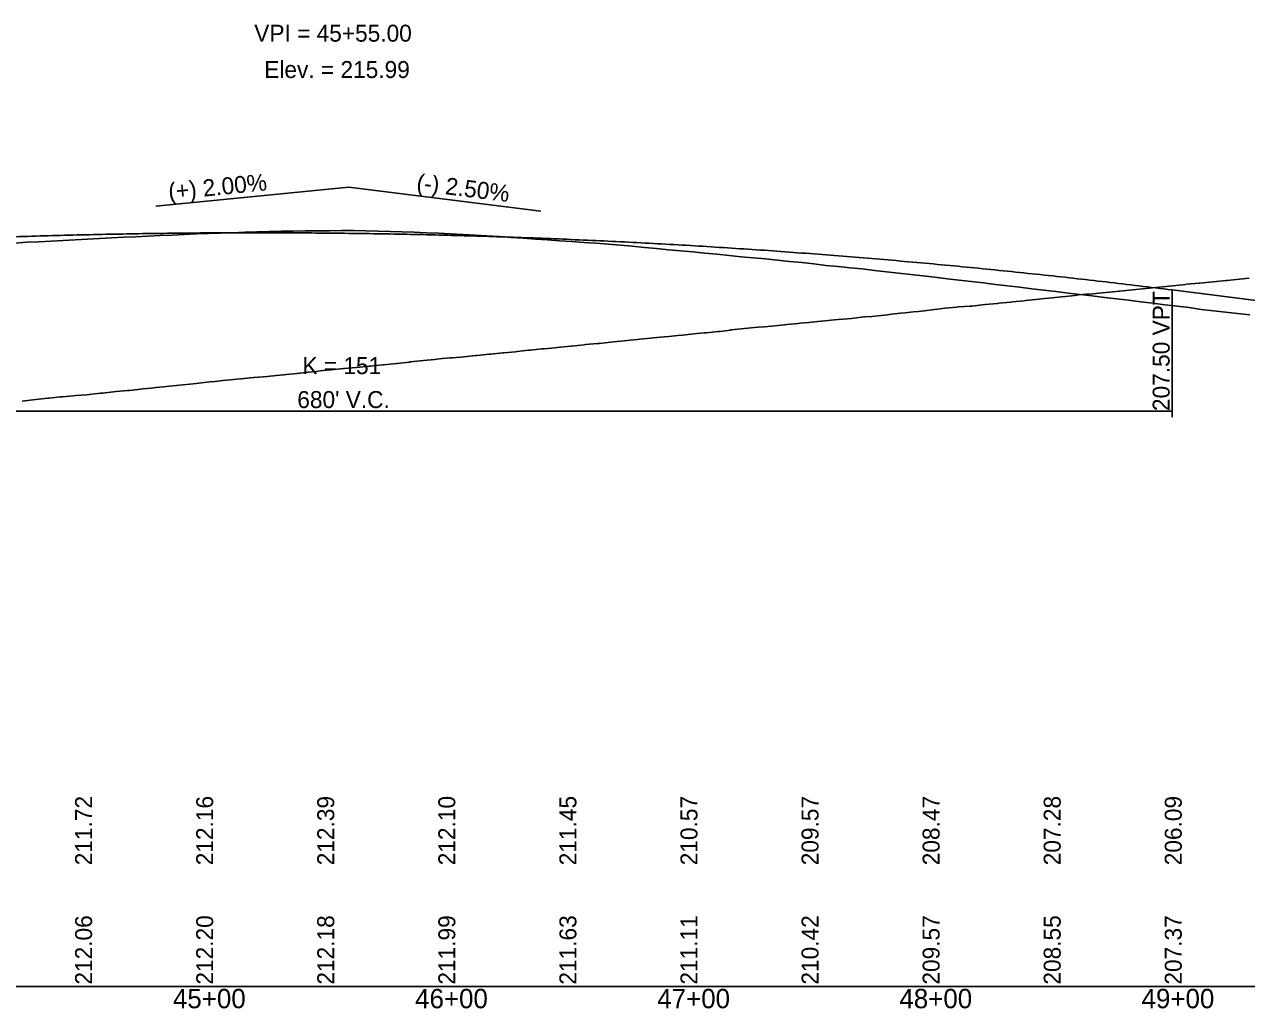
# Model space of a CAD drawing. Extents: x 1876258 to 1932803, y 754739 to 837911.
# Drawn here: x 1881084 to 1881589, y 820541 to 820947 of the extents above; entities that cross this region are included whole.
import ezdxf

# ---------------------------------------------------------------- set-up
doc = ezdxf.new("R2010")
doc.units = 0
for name, color, linetype in [('RD_DDB_GradeTX', 7, 'Continuous'), ('RD_DDB_Profile_EX', 7, 'Continuous'), ('RD_DDB_Profile_Lbl', 7, 'Continuous'), ('RD_DDB_Profile_PR', 7, 'Continuous'), ('RD_DDB_StaTX', 7, 'Continuous'), ('RD_DDB_StripGrade', 7, 'Continuous'), ('RD_DDB_VCLbl', 7, 'Continuous'), ('RD_GPK_Profile_Cell', 7, 'Continuous'), ('RD_Sketch1', 7, 'Continuous')]:
    doc.layers.add(name, color=color, linetype=linetype)

msp = doc.modelspace()

# ---------------------------------------------------------------- linework, layer by layer
at = {"layer": 'RD_DDB_GradeTX'}
for p in [(1881138.48, 820872.1), (1881297.46, 820870.14)]:
    msp.add_line(p, (1881218.08, 820880.06), dxfattribs=at)
at = {"layer": 'RD_DDB_Profile_EX'}
for points in [[(1881080.15, 820856.96), (1881085.15, 820857.27), (1881090.15, 820857.49), (1881095.15, 820857.72), (1881100.15, 820858), (1881105.15, 820858.27), (1881110.15, 820858.55), (1881115.15, 820858.83), (1881120.15, 820859.08), (1881125.15, 820859.32), (1881130.15, 820859.57), (1881135.15, 820859.85), (1881140.15, 820860.05), (1881145.15, 820860.26), (1881150.15, 820860.48), (1881155.15, 820860.71), (1881160.15, 820860.84), (1881165.15, 820860.96), (1881170.15, 820861.17), (1881175.15, 820861.41), (1881180.15, 820861.58), (1881185.15, 820861.68), (1881190.15, 820861.79), (1881195.15, 820861.89), (1881200.15, 820861.95), (1881205.15, 820862.01), (1881210.15, 820862.05), (1881215.15, 820862.06), (1881220.15, 820862.06), (1881225.15, 820862.01), (1881230.15, 820861.87), (1881235.15, 820861.72), (1881240.15, 820861.55), (1881245.15, 820861.37), (1881250.15, 820861.17), (1881255.15, 820860.97), (1881260.15, 820860.78), (1881265.15, 820860.53), (1881270.15, 820860.24), (1881275.15, 820859.95), (1881280.15, 820859.62), (1881285.15, 820859.28), (1881290.15, 820858.93), (1881295.15, 820858.58), (1881300.15, 820858.24), (1881305.15, 820857.9), (1881310.15, 820857.55), (1881315.15, 820857.21), (1881320.15, 820856.84), (1881325.15, 820856.44), (1881330.15, 820856.05), (1881335.15, 820855.61), (1881340.15, 820855.15), (1881345.15, 820854.67), (1881350.15, 820854.15), (1881355.15, 820853.68), (1881360.15, 820853.26), (1881365.15, 820852.81), (1881370.15, 820852.29), (1881375.15, 820851.78), (1881380.15, 820851.32), (1881385.15, 820850.86), (1881390.15, 820850.37)], [(1881390.15, 820850.37), (1881395.15, 820849.87), (1881400.15, 820849.38), (1881405.15, 820848.89), (1881410.15, 820848.33), (1881415.15, 820847.74), (1881420.15, 820847.24), (1881425.15, 820846.78), (1881430.15, 820846.25), (1881435.15, 820845.65), (1881440.15, 820845.08), (1881445.15, 820844.54), (1881450.15, 820843.98), (1881455.15, 820843.39), (1881460.15, 820842.8), (1881465.15, 820842.21), (1881470.15, 820841.63), (1881475.15, 820841.05), (1881480.15, 820840.47), (1881485.15, 820839.85), (1881490.15, 820839.24), (1881495.15, 820838.68), (1881500.15, 820838.11), (1881505.15, 820837.49), (1881510.15, 820836.88), (1881515.15, 820836.29), (1881520.15, 820835.69), (1881525.15, 820835.11), (1881530.15, 820834.52), (1881535.15, 820833.93), (1881540.15, 820833.33), (1881545.15, 820832.72), (1881550.15, 820832.1), (1881555.15, 820831.51), (1881560.15, 820830.94), (1881565.15, 820830.29), (1881570.15, 820829.56), (1881575.15, 820828.9), (1881580.15, 820828.36), (1881585.15, 820827.81), (1881590.15, 820827.26)]]:
    msp.add_lwpolyline(points, dxfattribs=at)
at = {"layer": 'RD_DDB_Profile_PR'}
msp.add_line((1881558.08, 820837.6), (1882275.08, 820748.07), dxfattribs=at)
msp.add_spline([(1880878.08, 820846.1), (1880891.68, 820847.42), (1880905.28, 820848.69), (1880918.88, 820849.9), (1880932.48, 820851.04), (1880946.08, 820852.12), (1880959.68, 820853.15), (1880973.28, 820854.11), (1880986.88, 820855.01), (1881000.48, 820855.85), (1881014.08, 820856.62), (1881027.68, 820857.34), (1881041.28, 820858), (1881054.88, 820858.59), (1881068.48, 820859.12), (1881082.08, 820859.59), (1881095.68, 820860.01), (1881109.28, 820860.36), (1881122.88, 820860.64), (1881136.48, 820860.87), (1881150.08, 820861.04), (1881163.68, 820861.14), (1881177.28, 820861.19), (1881190.88, 820861.17), (1881204.48, 820861.09), (1881218.08, 820860.95), (1881231.68, 820860.75), (1881245.28, 820860.49), (1881258.88, 820860.17), (1881272.48, 820859.78), (1881286.08, 820859.34), (1881299.68, 820858.83), (1881313.28, 820858.26), (1881326.88, 820857.64), (1881340.48, 820856.95), (1881354.08, 820856.2), (1881367.68, 820855.38), (1881381.28, 820854.51), (1881394.88, 820853.58), (1881408.48, 820852.58), (1881422.08, 820851.53), (1881435.68, 820850.41), (1881449.28, 820849.23), (1881462.88, 820847.99), (1881476.48, 820846.69), (1881490.08, 820845.33), (1881503.68, 820843.9), (1881517.28, 820842.42), (1881530.88, 820840.88), (1881544.48, 820839.27), (1881558.08, 820837.6)], degree=3, dxfattribs=at)
at = {"layer": 'RD_DDB_VCLbl'}
for p, q in [((1881558.08, 820785.1), (1881558.08, 820837.6)), ((1880878.08, 820787.6), (1881558.08, 820787.6))]:
    msp.add_line(p, q, dxfattribs=at)
at = {"layer": 'RD_GPK_Profile_Cell'}
msp.add_line((1878363.08, 820550.13), (1884763.08, 820550.13), dxfattribs=at)
at = {"layer": 'RD_Sketch1'}
msp.add_lwpolyline([(1881083.28, 820791.71), (1881087.58, 820792.2), (1881088.79, 820792.34), (1881093.78, 820792.93), (1881094.34, 820792.98), (1881099.06, 820793.45), (1881099.89, 820793.52), (1881104.3, 820793.87), (1881105.4, 820793.96), (1881109.86, 820794.36), (1881110.9, 820794.47), (1881115.57, 820794.95), (1881116.42, 820795.04), (1881120.99, 820795.53), (1881121.97, 820795.61), (1881126.75, 820796.03), (1881127.47, 820796.11), (1881131.14, 820796.51), (1881132.99, 820796.71), (1881136.28, 820797.07), (1881138.53, 820797.28), (1881141.55, 820797.56), (1881144.05, 820797.81), (1881146.93, 820798.1), (1881149.56, 820798.39), (1881152.39, 820798.7), (1881155.08, 820799), (1881157.27, 820799.25), (1881160.61, 820799.6), (1881162.88, 820799.83), (1881166.13, 820800.19), (1881169.2, 820800.53), (1881171.67, 820800.76), (1881173.76, 820800.96), (1881177.21, 820801.25), (1881178.92, 820801.39), (1881182.73, 820801.72), (1881184.44, 820801.86), (1881188.24, 820802.23), (1881189.75, 820802.37), (1881193.76, 820802.77), (1881195.31, 820802.92), (1881199.27, 820803.36), (1881201.36, 820803.6), (1881204.79, 820803.98), (1881206.34, 820804.15), (1881210.32, 820804.56), (1881210.88, 820804.62), (1881215.85, 820805.11), (1881216.15, 820805.14), (1881221.21, 820805.6), (1881221.37, 820805.62), (1881226.45, 820806.12), (1881226.9, 820806.16), (1881232.11, 820806.66), (1881232.42, 820806.7), (1881237.94, 820807.24), (1881238.06, 820807.25), (1881243.2, 820807.85), (1881243.45, 820807.88), (1881248.92, 820808.49), (1881248.99, 820808.5), (1881253.59, 820808.94), (1881254.51, 820809.03), (1881256.75, 820809.27), (1881260.05, 820809.54), (1881260.79, 820809.6), (1881264.33, 820809.91), (1881265.56, 820810.03), (1881270.38, 820810.5), (1881271.09, 820810.57), (1881276.07, 820811.05), (1881276.61, 820811.1), (1881281.65, 820811.59), (1881282.13, 820811.64), (1881287.01, 820812.1), (1881287.64, 820812.17), (1881292.38, 820812.68), (1881293.17, 820812.77), (1881297.8, 820813.25), (1881298.72, 820813.32), (1881303.32, 820813.68), (1881304.21, 820813.78), (1881309.73, 820814.4), (1881310.09, 820814.44), (1881315.26, 820814.98), (1881315.92, 820815.05), (1881320.81, 820815.47), (1881321.68, 820815.55), (1881326.31, 820816.02), (1881327.62, 820816.15), (1881331.83, 820816.6), (1881334.35, 820816.86), (1881337.35, 820817.18), (1881338.12, 820817.26), (1881342.89, 820817.72), (1881343.67, 820817.79), (1881348.41, 820818.25), (1881350.29, 820818.43), (1881353.94, 820818.77), (1881355.9, 820818.95), (1881359.45, 820819.31), (1881361.85, 820819.55), (1881364.99, 820819.83), (1881365.85, 820819.91), (1881370.5, 820820.39), (1881371.42, 820820.48), (1881375.59, 820821.02), (1881376, 820821.07), (1881380.11, 820821.54), (1881381.54, 820821.69), (1881385.64, 820822.13), (1881387.11, 820822.23), (1881389.77, 820822.41), (1881392.62, 820822.64), (1881395.32, 820822.86), (1881398.09, 820823.19), (1881398.94, 820823.29), (1881403.65, 820823.74), (1881404.41, 820823.81), (1881408.1, 820824.2), (1881409.18, 820824.3), (1881413.21, 820824.65), (1881414.69, 820824.79), (1881418.71, 820825.19), (1881420.22, 820825.33), (1881424.08, 820825.68), (1881425.72, 820825.86), (1881429.79, 820826.3), (1881431.27, 820826.43), (1881434.12, 820826.68), (1881436.78, 820826.95), (1881440.56, 820827.34), (1881442.28, 820827.54), (1881445.87, 820827.96), (1881447.82, 820828.16), (1881451.1, 820828.49), (1881453.35, 820828.72), (1881456.85, 820829.08), (1881458.83, 820829.34), (1881462.28, 820829.81), (1881464.39, 820830.02), (1881469.06, 820830.5), (1881469.96, 820830.56), (1881474.65, 820830.86), (1881475.43, 820830.94), (1881480.76, 820831.53), (1881480.97, 820831.55), (1881485.99, 820832.05), (1881486.49, 820832.1), (1881491.56, 820832.61), (1881492.01, 820832.65), (1881497.07, 820833.15), (1881497.53, 820833.2), (1881503.06, 820833.76), (1881504.09, 820833.86), (1881508.58, 820834.3), (1881512.49, 820834.68), (1881514.08, 820834.87), (1881517.91, 820835.33), (1881519.62, 820835.52), (1881522.43, 820835.82), (1881525.17, 820836.05), (1881526.54, 820836.16), (1881530.68, 820836.55), (1881532.41, 820836.71), (1881536.19, 820837.11), (1881536.54, 820837.15), (1881540.47, 820837.53), (1881541.72, 820837.66), (1881547.25, 820838.2), (1881547.35, 820838.21), (1881552.76, 820838.77), (1881552.83, 820838.78), (1881558.29, 820839.33), (1881558.33, 820839.33), (1881563.81, 820839.9), (1881563.88, 820839.91), (1881569.34, 820840.43), (1881569.56, 820840.45), (1881574.87, 820840.95), (1881575.1, 820840.97), (1881580.38, 820841.5), (1881580.82, 820841.55), (1881584.57, 820841.94), (1881585.92, 820842.05), (1881589.88, 820842.39)], dxfattribs=at)
msp.add_lwpolyline([(1881083.28, 820791.71), (1881087.58, 820792.2), (1881088.79, 820792.34), (1881093.78, 820792.93), (1881094.34, 820792.98), (1881099.06, 820793.45), (1881099.89, 820793.52), (1881104.3, 820793.87), (1881105.4, 820793.96), (1881109.86, 820794.36), (1881110.9, 820794.47), (1881115.57, 820794.95), (1881116.42, 820795.04), (1881120.99, 820795.53), (1881121.97, 820795.61), (1881126.75, 820796.03), (1881127.47, 820796.11), (1881131.14, 820796.51), (1881132.99, 820796.71), (1881136.28, 820797.07), (1881138.53, 820797.28), (1881141.55, 820797.56), (1881144.05, 820797.81), (1881146.93, 820798.1), (1881149.56, 820798.39), (1881152.39, 820798.7), (1881155.08, 820799), (1881157.27, 820799.25), (1881160.61, 820799.6), (1881162.88, 820799.83), (1881166.13, 820800.19), (1881169.2, 820800.53), (1881171.67, 820800.76), (1881173.76, 820800.96), (1881177.21, 820801.25), (1881178.92, 820801.39), (1881182.73, 820801.72), (1881184.44, 820801.86), (1881188.24, 820802.23), (1881189.75, 820802.37), (1881193.76, 820802.77), (1881195.31, 820802.92), (1881199.27, 820803.36), (1881201.36, 820803.6), (1881204.79, 820803.98), (1881206.34, 820804.15), (1881210.32, 820804.56), (1881210.88, 820804.62), (1881215.85, 820805.11), (1881216.15, 820805.14), (1881221.21, 820805.6), (1881221.37, 820805.62), (1881226.45, 820806.12), (1881226.9, 820806.16), (1881232.11, 820806.66), (1881232.42, 820806.7), (1881237.94, 820807.24), (1881238.06, 820807.25), (1881243.2, 820807.85), (1881243.45, 820807.88), (1881248.92, 820808.49), (1881248.99, 820808.5), (1881253.59, 820808.94), (1881254.51, 820809.03), (1881256.75, 820809.27), (1881260.05, 820809.54), (1881260.79, 820809.6), (1881264.33, 820809.91), (1881265.56, 820810.03), (1881270.38, 820810.5), (1881271.09, 820810.57), (1881276.07, 820811.05), (1881276.61, 820811.1), (1881281.65, 820811.59), (1881282.13, 820811.64), (1881287.01, 820812.1), (1881287.64, 820812.17), (1881292.38, 820812.68), (1881293.17, 820812.77), (1881297.8, 820813.25), (1881298.72, 820813.32), (1881303.32, 820813.68), (1881304.21, 820813.78), (1881309.73, 820814.4), (1881310.09, 820814.44), (1881315.26, 820814.98), (1881315.92, 820815.05), (1881320.81, 820815.47), (1881321.68, 820815.55), (1881326.31, 820816.02), (1881327.62, 820816.15), (1881331.83, 820816.6), (1881334.35, 820816.86), (1881337.35, 820817.18), (1881338.12, 820817.26), (1881342.89, 820817.72), (1881343.67, 820817.79), (1881348.41, 820818.25), (1881350.29, 820818.43), (1881353.94, 820818.77), (1881355.9, 820818.95), (1881359.45, 820819.31), (1881361.85, 820819.55), (1881364.99, 820819.83), (1881365.85, 820819.91), (1881370.5, 820820.39), (1881371.42, 820820.48), (1881375.59, 820821.02), (1881376, 820821.07), (1881380.11, 820821.54), (1881381.54, 820821.69), (1881385.64, 820822.13), (1881387.11, 820822.23), (1881389.77, 820822.41), (1881392.62, 820822.64), (1881395.32, 820822.86), (1881398.09, 820823.19), (1881398.94, 820823.29), (1881403.65, 820823.74), (1881404.41, 820823.81), (1881408.1, 820824.2), (1881409.18, 820824.3), (1881413.21, 820824.65), (1881414.69, 820824.79), (1881418.71, 820825.19), (1881420.22, 820825.33), (1881424.08, 820825.68), (1881425.72, 820825.86), (1881429.79, 820826.3), (1881431.27, 820826.43), (1881434.12, 820826.68), (1881436.78, 820826.95), (1881440.56, 820827.34), (1881442.28, 820827.54), (1881445.87, 820827.96), (1881447.82, 820828.16), (1881451.1, 820828.49), (1881453.35, 820828.72), (1881456.85, 820829.08), (1881458.83, 820829.34), (1881462.28, 820829.81), (1881464.39, 820830.02), (1881469.06, 820830.5), (1881469.96, 820830.56), (1881474.65, 820830.86), (1881475.43, 820830.94), (1881480.76, 820831.53), (1881480.97, 820831.55), (1881485.99, 820832.05), (1881486.49, 820832.1), (1881491.56, 820832.61), (1881492.01, 820832.65), (1881497.07, 820833.15), (1881497.53, 820833.2), (1881503.06, 820833.76), (1881504.09, 820833.86), (1881508.58, 820834.3), (1881512.49, 820834.68), (1881514.08, 820834.87), (1881517.91, 820835.33), (1881519.62, 820835.52), (1881522.43, 820835.82), (1881525.17, 820836.05), (1881526.54, 820836.16), (1881530.68, 820836.55), (1881532.41, 820836.71), (1881536.19, 820837.11), (1881536.54, 820837.15), (1881540.47, 820837.53), (1881541.72, 820837.66), (1881547.25, 820838.2), (1881547.35, 820838.21), (1881552.76, 820838.77), (1881552.83, 820838.78), (1881558.29, 820839.33), (1881558.33, 820839.33), (1881563.81, 820839.9), (1881563.88, 820839.91), (1881569.34, 820840.43), (1881569.56, 820840.45), (1881574.87, 820840.95), (1881575.1, 820840.97), (1881580.38, 820841.5), (1881580.82, 820841.55), (1881584.57, 820841.94), (1881585.92, 820842.05), (1881589.88, 820842.39)], dxfattribs=at)
msp.add_lwpolyline([(1881083.28, 820791.71), (1881087.58, 820792.2), (1881088.79, 820792.34), (1881093.78, 820792.93), (1881094.34, 820792.98), (1881099.06, 820793.45), (1881099.89, 820793.52), (1881104.3, 820793.87), (1881105.4, 820793.96), (1881109.86, 820794.36), (1881110.9, 820794.47), (1881115.57, 820794.95), (1881116.42, 820795.04), (1881120.99, 820795.53), (1881121.97, 820795.61), (1881126.75, 820796.03), (1881127.47, 820796.11), (1881131.14, 820796.51), (1881132.99, 820796.71), (1881136.28, 820797.07), (1881138.53, 820797.28), (1881141.55, 820797.56), (1881144.05, 820797.81), (1881146.93, 820798.1), (1881149.56, 820798.39), (1881152.39, 820798.7), (1881155.08, 820799), (1881157.27, 820799.25), (1881160.61, 820799.6), (1881162.88, 820799.83), (1881166.13, 820800.19), (1881169.2, 820800.53), (1881171.67, 820800.76), (1881173.76, 820800.96), (1881177.21, 820801.25), (1881178.92, 820801.39), (1881182.73, 820801.72), (1881184.44, 820801.86), (1881188.24, 820802.23), (1881189.75, 820802.37), (1881193.76, 820802.77), (1881195.31, 820802.92), (1881199.27, 820803.36), (1881201.36, 820803.6), (1881204.79, 820803.98), (1881206.34, 820804.15), (1881210.32, 820804.56), (1881210.88, 820804.62), (1881215.85, 820805.11), (1881216.15, 820805.14), (1881221.21, 820805.6), (1881221.37, 820805.62), (1881226.45, 820806.12), (1881226.9, 820806.16), (1881232.11, 820806.66), (1881232.42, 820806.7), (1881237.94, 820807.24), (1881238.06, 820807.25), (1881243.2, 820807.85), (1881243.45, 820807.88), (1881248.92, 820808.49), (1881248.99, 820808.5), (1881253.59, 820808.94), (1881254.51, 820809.03), (1881256.75, 820809.27), (1881260.05, 820809.54), (1881260.79, 820809.6), (1881264.33, 820809.91), (1881265.56, 820810.03), (1881270.38, 820810.5), (1881271.09, 820810.57), (1881276.07, 820811.05), (1881276.61, 820811.1), (1881281.65, 820811.59), (1881282.13, 820811.64), (1881287.01, 820812.1), (1881287.64, 820812.17), (1881292.38, 820812.68), (1881293.17, 820812.77), (1881297.8, 820813.25), (1881298.72, 820813.32), (1881303.32, 820813.68), (1881304.21, 820813.78), (1881309.73, 820814.4), (1881310.09, 820814.44), (1881315.26, 820814.98), (1881315.92, 820815.05), (1881320.81, 820815.47), (1881321.68, 820815.55), (1881326.31, 820816.02), (1881327.62, 820816.15), (1881331.83, 820816.6), (1881334.35, 820816.86), (1881337.35, 820817.18), (1881338.12, 820817.26), (1881342.89, 820817.72), (1881343.67, 820817.79), (1881348.41, 820818.25), (1881350.29, 820818.43), (1881353.94, 820818.77), (1881355.9, 820818.95), (1881359.45, 820819.31), (1881361.85, 820819.55), (1881364.99, 820819.83), (1881365.85, 820819.91), (1881370.5, 820820.39), (1881371.42, 820820.48), (1881375.59, 820821.02), (1881376, 820821.07), (1881380.11, 820821.54), (1881381.54, 820821.69), (1881385.64, 820822.13), (1881387.11, 820822.23), (1881389.77, 820822.41), (1881392.62, 820822.64), (1881395.32, 820822.86), (1881398.09, 820823.19), (1881398.94, 820823.29), (1881403.65, 820823.74), (1881404.41, 820823.81), (1881408.1, 820824.2), (1881409.18, 820824.3), (1881413.21, 820824.65), (1881414.69, 820824.79), (1881418.71, 820825.19), (1881420.22, 820825.33), (1881424.08, 820825.68), (1881425.72, 820825.86), (1881429.79, 820826.3), (1881431.27, 820826.43), (1881434.12, 820826.68), (1881436.78, 820826.95), (1881440.56, 820827.34), (1881442.28, 820827.54), (1881445.87, 820827.96), (1881447.82, 820828.16), (1881451.1, 820828.49), (1881453.35, 820828.72), (1881456.85, 820829.08), (1881458.83, 820829.34), (1881462.28, 820829.81), (1881464.39, 820830.02), (1881469.06, 820830.5), (1881469.96, 820830.56), (1881474.65, 820830.86), (1881475.43, 820830.94), (1881480.76, 820831.53), (1881480.97, 820831.55), (1881485.99, 820832.05), (1881486.49, 820832.1), (1881491.56, 820832.61), (1881492.01, 820832.65), (1881497.07, 820833.15), (1881497.53, 820833.2), (1881503.06, 820833.76), (1881504.09, 820833.86), (1881508.58, 820834.3), (1881512.49, 820834.68), (1881514.08, 820834.87), (1881517.91, 820835.33), (1881519.62, 820835.52), (1881522.43, 820835.82), (1881525.17, 820836.05), (1881526.54, 820836.16), (1881530.68, 820836.55), (1881532.41, 820836.71), (1881536.19, 820837.11), (1881536.54, 820837.15), (1881540.47, 820837.53), (1881541.72, 820837.66), (1881547.25, 820838.2), (1881547.35, 820838.21), (1881552.76, 820838.77), (1881552.83, 820838.78), (1881558.29, 820839.33), (1881558.33, 820839.33), (1881563.81, 820839.9), (1881563.88, 820839.91), (1881569.34, 820840.43), (1881569.56, 820840.45), (1881574.87, 820840.95), (1881575.1, 820840.97), (1881580.38, 820841.5), (1881580.82, 820841.55), (1881584.57, 820841.94), (1881585.92, 820842.05), (1881589.88, 820842.39)], dxfattribs=at)

# ---------------------------------------------------------------- texts
at = {"layer": 'RD_DDB_GradeTX'}
for s, rotation, p in [('(+) 2.00%', 5.7036, (1881143.92, 820874.66)), ('(-) 2.50%', 352.8826, (1881245.8, 820878.61))]:
    msp.add_text(s, height=7, rotation=rotation, dxfattribs=at).set_placement(p)
at = {"layer": 'RD_DDB_Profile_Lbl'}
for s, p in [('VPI = 45+55.00', (1881179.06, 820940.06)), ('Elev. = 215.99', (1881183.19, 820925.06))]:
    msp.add_text(s, height=7, dxfattribs=at).set_placement(p)
at = {"layer": 'RD_DDB_StaTX'}
for s, p in [('45+00', (1881145.49, 820541.13)), ('46+00', (1881245.49, 820541.13)), ('47+00', (1881345.49, 820541.13)), ('48+00', (1881445.49, 820541.13)), ('49+00', (1881545.49, 820541.13))]:
    msp.add_text(s, height=8, dxfattribs=at).set_placement(p)
at = {"layer": 'RD_DDB_StripGrade'}
for s, p in [('207.50 VPT', (1881557.08, 820787.6)), ('211.72', (1881112.08, 820600.13)), ('212.16', (1881162.08, 820600.13)), ('212.39', (1881212.08, 820600.13)), ('212.10', (1881262.08, 820600.13)), ('211.45', (1881312.08, 820600.13)), ('210.57', (1881362.08, 820600.13)), ('209.57', (1881412.08, 820600.13)), ('208.47', (1881462.08, 820600.13)), ('207.28', (1881512.08, 820600.13)), ('206.09', (1881562.08, 820600.13)), ('212.06', (1881112.08, 820550.88)), ('212.20', (1881162.08, 820550.88)), ('212.18', (1881212.08, 820550.88)), ('211.99', (1881262.08, 820550.88)), ('211.63', (1881312.08, 820550.88)), ('211.11', (1881362.08, 820550.88)), ('210.42', (1881412.08, 820550.88)), ('209.57', (1881462.08, 820550.88)), ('208.55', (1881512.08, 820550.88)), ('207.37', (1881562.08, 820550.88))]:
    msp.add_text(s, height=7, rotation=90, dxfattribs=at).set_placement(p)
at = {"layer": 'RD_DDB_VCLbl'}
for s, p in [('K = 151', (1881198.95, 820802.85)), ("680' V.C.", (1881196.83, 820788.85))]:
    msp.add_text(s, height=7, dxfattribs=at).set_placement(p)

doc.saveas('drawing.dxf')
